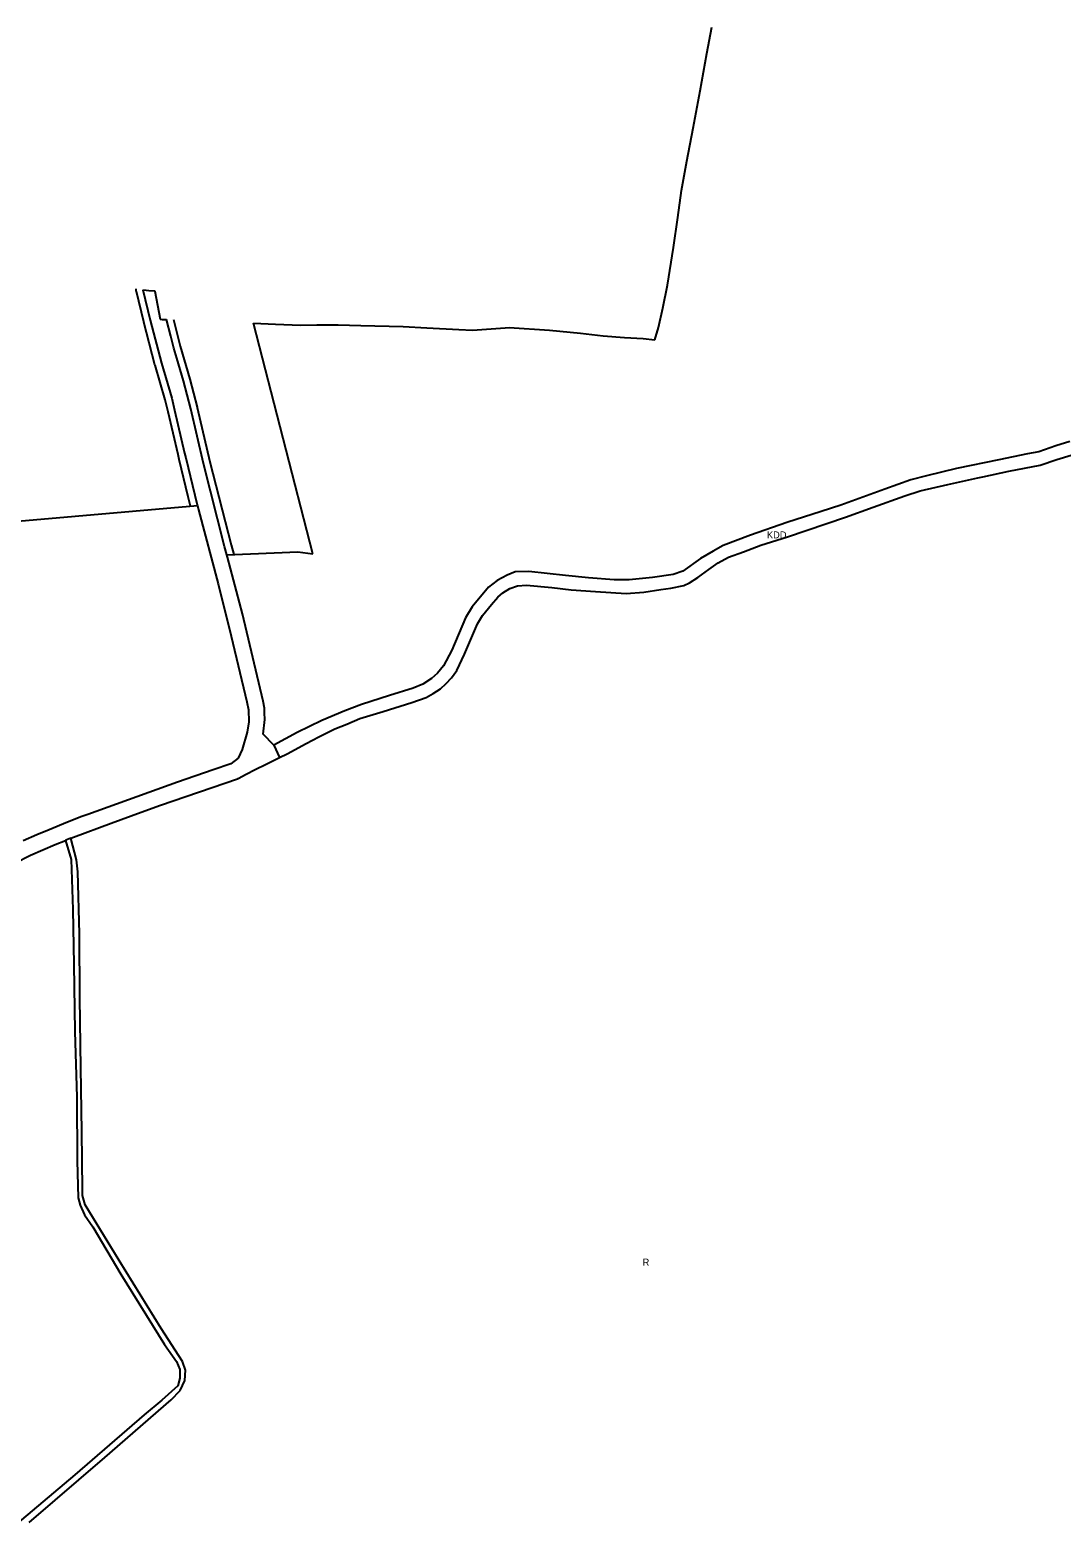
# Model space of a CAD drawing. Extents: x 7435758 to 7439981, y 5550649 to 5554049.
# Drawn here: x 7438238 to 7439010, y 5551717 to 5552845 of the extents above; entities that cross this region are included whole.
import ezdxf

# ---------------------------------------------------------------- set-up
doc = ezdxf.new("R2010")
doc.units = 0
for name, color, linetype in [('linie_rozgraniczające', 7, 'Continuous'), ('linie_zabudowy_nieprzekraczalne', 7, 'Continuous'), ('oznaczenia_przeznaczen', 7, 'Continuous')]:
    doc.layers.add(name, color=color, linetype=linetype)

msp = doc.modelspace()

# ---------------------------------------------------------------- linework, layer by layer
at = {"layer": 'linie_rozgraniczające'}
for p, q in [((7438744.68, 5552827.83), (7438748.26, 5552847.53)), ((7438739.56, 5552800.01), (7438744.68, 5552827.83)), ((7438734.37, 5552772.19), (7438739.56, 5552800.01)), ((7438729.69, 5552747.32), (7438734.37, 5552772.19)), ((7438725.79, 5552725.47), (7438729.69, 5552747.32)), ((7438722.9, 5552705.16), (7438725.79, 5552725.47)), ((7438719.67, 5552682.88), (7438722.9, 5552705.16)), ((7438715.25, 5552654.67), (7438719.67, 5552682.88)), ((7438711.74, 5552637.38), (7438715.25, 5552654.67)), ((7438322.72, 5552651.12), (7438328.21, 5552628.27)), ((7438322.72, 5552651.12), (7438325.27, 5552650.78)), ((7438325.27, 5552650.78), (7438327.16, 5552650.65)), ((7438327.16, 5552650.65), (7438331.61, 5552650.33)), ((7438331.61, 5552650.33), (7438331.68, 5552649.99)), ((7438331.68, 5552649.99), (7438335.75, 5552629.06)), ((7438708.52, 5552622.89), (7438711.74, 5552637.38)), ((7438328.21, 5552628.27), (7438336.63, 5552596.18)), ((7438335.75, 5552629.06), (7438337.23, 5552629)), ((7438337.23, 5552629), (7438340.17, 5552628.88)), ((7438340.17, 5552628.88), (7438340.45, 5552628.87)), ((7438343.56, 5552616.42), (7438340.45, 5552628.87)), ((7438449.92, 5552453.64), (7438405.44, 5552626.22)), ((7438405.44, 5552626.22), (7438421.86, 5552625.49)), ((7438421.86, 5552625.49), (7438440.58, 5552624.67)), ((7438440.58, 5552624.67), (7438452.74, 5552624.8)), ((7438452.74, 5552624.8), (7438468.8, 5552624.98)), ((7438468.8, 5552624.98), (7438485.76, 5552624.5)), ((7438485.76, 5552624.5), (7438517.51, 5552623.61)), ((7438517.51, 5552623.61), (7438535.23, 5552622.71)), ((7438535.23, 5552622.71), (7438559.17, 5552621.48)), ((7438559.17, 5552621.48), (7438569.23, 5552620.97)), ((7438569.23, 5552620.97), (7438593.66, 5552622.75)), ((7438593.66, 5552622.75), (7438596.63, 5552622.97)), ((7438596.63, 5552622.97), (7438626.87, 5552620.99)), ((7438626.87, 5552620.99), (7438650.03, 5552618.68)), ((7438705.83, 5552613.59), (7438708.52, 5552622.89)), ((7438345.77, 5552607.54), (7438343.56, 5552616.42)), ((7438650.03, 5552618.68), (7438667.19, 5552616.72)), ((7438667.19, 5552616.72), (7438683.12, 5552615.39)), ((7438683.12, 5552615.39), (7438697.04, 5552614.6)), ((7438697.04, 5552614.6), (7438705.83, 5552613.59)), ((7438348.01, 5552600.01), (7438345.77, 5552607.54)), ((7438353.1, 5552582.88), (7438348.01, 5552600.01)), ((7438348.01, 5552600.01), (7438348.01, 5552600.01)), ((7438336.63, 5552596.18), (7438344.29, 5552569.96)), ((7438358.55, 5552561.94), (7438353.1, 5552582.88)), ((7438344.29, 5552569.96), (7438346.43, 5552561.05)), ((7438346.43, 5552561.05), (7438353.93, 5552528.9)), ((7438367.99, 5552521.18), (7438358.55, 5552561.94)), ((7438992.94, 5552529.86), (7438984.57, 5552528.4)), ((7439005.75, 5552534.23), (7438992.94, 5552529.86)), ((7439016.18, 5552537.5), (7439005.75, 5552534.23)), ((7438353.93, 5552528.9), (7438354.75, 5552525.29)), ((7438354.75, 5552525.29), (7438361.51, 5552497.38)), ((7438383.86, 5552459.09), (7438367.99, 5552521.18)), ((7438963.04, 5552523.87), (7438931.43, 5552517.31)), ((7438984.57, 5552528.4), (7438963.04, 5552523.87)), ((7438970.59, 5552515.35), (7438994.06, 5552519.85)), ((7438994.06, 5552519.85), (7439006.47, 5552524.22)), ((7439006.47, 5552524.22), (7439017.3, 5552527.29)), ((7438897.36, 5552508.93), (7438877.74, 5552502.04)), ((7438909.02, 5552511.84), (7438897.36, 5552508.93)), ((7438931.43, 5552517.31), (7438909.02, 5552511.84)), ((7438924.91, 5552505.38), (7438947.45, 5552510.35)), ((7438947.45, 5552510.35), (7438951.13, 5552511.15)), ((7438951.13, 5552511.15), (7438970.59, 5552515.35)), ((7438361.51, 5552497.38), (7438363.37, 5552490.22)), ((7438877.74, 5552502.04), (7438844.94, 5552489.95)), ((7438869.06, 5552488.39), (7438892.66, 5552497.06)), ((7438892.66, 5552497.06), (7438904.29, 5552500.78)), ((7438904.29, 5552500.78), (7438924.91, 5552505.38)), ((7438223.43, 5552477.5), (7438363.49, 5552489.76)), ((7438363.37, 5552490.22), (7438363.49, 5552489.76)), ((7438363.49, 5552489.76), (7438364.33, 5552486.5)), ((7438364.33, 5552486.5), (7438378.95, 5552431.14)), ((7438830.21, 5552485.19), (7438804.56, 5552477.05)), ((7438844.94, 5552489.95), (7438830.21, 5552485.19)), ((7438848.25, 5552480.85), (7438869.06, 5552488.39)), ((7438804.56, 5552477.05), (7438777.33, 5552467.62)), ((7438804.9, 5552466.2), (7438848.25, 5552480.85)), ((7438777.33, 5552467.62), (7438756.74, 5552459.68)), ((7438785.05, 5552459.91), (7438804.9, 5552466.2)), ((7438385.56, 5552452.77), (7438383.86, 5552459.09)), ((7438385.56, 5552452.77), (7438438.57, 5552454.92)), ((7438386.03, 5552450.99), (7438385.56, 5552452.77)), ((7438397.17, 5552408.54), (7438386.03, 5552450.99)), ((7438438.57, 5552454.92), (7438449.92, 5552453.64)), ((7438749.3, 5552455.62), (7438739.98, 5552449.96)), ((7438756.74, 5552459.68), (7438749.3, 5552455.62)), ((7438753.21, 5552446.74), (7438760.96, 5552450.92)), ((7438760.96, 5552450.92), (7438772.06, 5552454.92)), ((7438772.06, 5552454.92), (7438785.05, 5552459.91)), ((7438601.22, 5552440.17), (7438595.23, 5552437.69)), ((7438611.56, 5552440.39), (7438601.22, 5552440.17)), ((7438638.89, 5552437.23), (7438611.56, 5552440.39)), ((7438726.77, 5552440.49), (7438719.55, 5552438.17)), ((7438739.98, 5552449.96), (7438726.77, 5552440.49)), ((7438737.82, 5552435.77), (7438746.1, 5552441.79)), ((7438746.1, 5552441.79), (7438753.21, 5552446.74)), ((7438378.95, 5552431.14), (7438388.86, 5552391.88)), ((7438581.18, 5552428.6), (7438569.1, 5552413.8)), ((7438587.88, 5552433.54), (7438581.18, 5552428.6)), ((7438595.23, 5552437.69), (7438587.88, 5552433.54)), ((7438597.26, 5552427.63), (7438602.86, 5552429.68)), ((7438602.86, 5552429.68), (7438609.74, 5552430.16)), ((7438609.74, 5552430.16), (7438628.59, 5552428.39)), ((7438628.59, 5552428.39), (7438643.08, 5552426.54)), ((7438656.02, 5552435.49), (7438638.89, 5552437.23)), ((7438675.36, 5552434.04), (7438656.02, 5552435.49)), ((7438686.63, 5552433.99), (7438675.36, 5552434.04)), ((7438704.01, 5552435.92), (7438686.63, 5552433.99)), ((7438719.55, 5552438.17), (7438704.01, 5552435.92)), ((7438717.64, 5552427.84), (7438727.5, 5552429.87)), ((7438727.5, 5552429.87), (7438731.68, 5552431.86)), ((7438731.68, 5552431.86), (7438737.82, 5552435.77)), ((7438583.53, 5552415.7), (7438588.18, 5552421.17)), ((7438588.18, 5552421.17), (7438592.11, 5552424.37)), ((7438592.11, 5552424.37), (7438597.26, 5552427.63)), ((7438643.08, 5552426.54), (7438661.41, 5552425.26)), ((7438661.41, 5552425.26), (7438684.2, 5552423.74)), ((7438684.2, 5552423.74), (7438697.56, 5552424.9)), ((7438697.56, 5552424.9), (7438710.17, 5552426.73)), ((7438710.17, 5552426.73), (7438717.64, 5552427.84)), ((7438412.69, 5552343.18), (7438397.17, 5552408.54)), ((7438564.15, 5552405.68), (7438553.96, 5552381.51)), ((7438569.1, 5552413.8), (7438564.15, 5552405.68)), ((7438573.16, 5552401.07), (7438576.76, 5552407.51)), ((7438576.76, 5552407.51), (7438583.53, 5552415.7)), ((7438563.32, 5552378.54), (7438573.16, 5552401.07)), ((7438388.86, 5552391.88), (7438400.52, 5552342.83)), ((7438553.96, 5552381.51), (7438547.54, 5552369.68)), ((7438557.52, 5552366.33), (7438563.32, 5552378.54)), ((7438543.19, 5552364.33), (7438538.68, 5552360.29)), ((7438547.54, 5552369.68), (7438543.19, 5552364.33)), ((7438549.7, 5552356.57), (7438553.49, 5552360.68)), ((7438553.49, 5552360.68), (7438557.52, 5552366.33)), ((7438524.97, 5552353.03), (7438507.13, 5552347.43)), ((7438532.16, 5552355.96), (7438524.97, 5552353.03)), ((7438538.68, 5552360.29), (7438532.16, 5552355.96)), ((7438534.69, 5552346.02), (7438539.85, 5552349.07)), ((7438539.85, 5552349.07), (7438545.39, 5552352.54)), ((7438545.39, 5552352.54), (7438549.7, 5552356.57)), ((7438400.52, 5552342.83), (7438401.75, 5552336.76)), ((7438413.7, 5552338.09), (7438412.69, 5552343.18)), ((7438413.82, 5552334.54), (7438413.7, 5552338.09)), ((7438486.29, 5552340.7), (7438473.69, 5552336.13)), ((7438507.13, 5552347.43), (7438486.29, 5552340.7)), ((7438502.43, 5552335.57), (7438523.88, 5552342.33)), ((7438523.88, 5552342.33), (7438534.69, 5552346.02)), ((7438402.02, 5552327.94), (7438400.8, 5552320.12)), ((7438401.75, 5552336.76), (7438402.02, 5552327.94)), ((7438412.72, 5552318.69), (7438413.98, 5552329.47)), ((7438413.98, 5552329.47), (7438413.82, 5552334.54)), ((7438456.62, 5552328.84), (7438438.11, 5552319.77)), ((7438473.69, 5552336.13), (7438456.62, 5552328.84)), ((7438475.41, 5552326.15), (7438484.99, 5552330.19)), ((7438484.99, 5552330.19), (7438502.43, 5552335.57)), ((7438400.8, 5552320.12), (7438397.03, 5552307.09)), ((7438420.65, 5552310.35), (7438412.72, 5552318.69)), ((7438438.11, 5552319.77), (7438420.65, 5552310.35)), ((7438445, 5552311.58), (7438454.38, 5552316.67)), ((7438454.38, 5552316.67), (7438466.32, 5552322.64)), ((7438466.32, 5552322.64), (7438475.41, 5552326.15)), ((7438397.03, 5552307.09), (7438393.96, 5552300.74)), ((7438420.65, 5552310.35), (7438424.93, 5552301.01)), ((7438430.74, 5552303.92), (7438445, 5552311.58)), ((7438388.52, 5552296.28), (7438375.38, 5552291.85)), ((7438393.96, 5552300.74), (7438388.52, 5552296.28)), ((7438406.66, 5552292.22), (7438415.03, 5552296.03)), ((7438415.03, 5552296.03), (7438424.93, 5552301.01)), ((7438424.93, 5552301.01), (7438430.74, 5552303.92)), ((7438348.58, 5552282.69), (7438281.6, 5552258.57)), ((7438335.94, 5552265.42), (7438393.4, 5552285.26)), ((7438375.38, 5552291.85), (7438348.58, 5552282.69)), ((7438393.4, 5552285.26), (7438393.55, 5552285.35)), ((7438393.55, 5552285.35), (7438394, 5552285.5)), ((7438394, 5552285.5), (7438399.99, 5552288.78)), ((7438399.99, 5552288.78), (7438406.66, 5552292.22)), ((7438298.99, 5552252.1), (7438321.51, 5552260.24)), ((7438321.51, 5552260.24), (7438335.94, 5552265.42)), ((7438266.33, 5552252.72), (7438252.54, 5552247.07)), ((7438277.12, 5552256.96), (7438266.33, 5552252.72)), ((7438270.73, 5552241.55), (7438298.99, 5552252.1)), ((7438277.13, 5552256.96), (7438277.12, 5552256.96)), ((7438281.6, 5552258.57), (7438277.13, 5552256.96)), ((7438243.46, 5552243.15), (7438233.29, 5552238.74)), ((7438252.54, 5552247.07), (7438243.46, 5552243.15)), ((7438257.14, 5552235.99), (7438264.74, 5552239.1)), ((7438265.08, 5552239.24), (7438264.74, 5552239.1)), ((7438264.74, 5552239.1), (7438269, 5552224.86)), ((7438268.72, 5552240.73), (7438265.08, 5552239.24)), ((7438268.72, 5552240.73), (7438270.73, 5552241.55)), ((7438272.96, 5552224.48), (7438268.72, 5552240.73)), ((7438226.89, 5552222), (7438238.58, 5552227.97)), ((7438238.58, 5552227.97), (7438257.14, 5552235.99)), ((7438269, 5552224.86), (7438270.34, 5552187.4)), ((7438273.96, 5552215.46), (7438272.96, 5552224.48)), ((7438275.21, 5552169.11), (7438273.96, 5552215.46)), ((7438270.34, 5552187.4), (7438271.11, 5552146.33)), ((7438275.64, 5552120.93), (7438275.21, 5552169.11)), ((7438271.11, 5552146.33), (7438271.8, 5552096.19)), ((7438276.4, 5552069.01), (7438275.64, 5552120.93)), ((7438271.8, 5552096.19), (7438273.35, 5552046.98)), ((7438276.99, 5552021.2), (7438276.4, 5552069.01)), ((7438273.35, 5552046.98), (7438273.57, 5551999.34)), ((7438277.58, 5551977.87), (7438276.99, 5552021.2)), ((7438273.57, 5551999.34), (7438274.25, 5551971.64)), ((7438277.59, 5551973.39), (7438277.58, 5551977.87)), ((7438274.25, 5551971.64), (7438275.73, 5551966.13)), ((7438275.73, 5551966.13), (7438279.07, 5551958.91)), ((7438279.66, 5551966.47), (7438277.59, 5551973.39)), ((7438304.96, 5551924.69), (7438279.66, 5551966.47)), ((7438279.07, 5551958.91), (7438285.18, 5551949.83)), ((7438285.18, 5551949.83), (7438306.27, 5551914.51)), ((7438336.37, 5551873.83), (7438304.96, 5551924.69)), ((7438306.27, 5551914.51), (7438339.01, 5551861.91)), ((7438352.27, 5551849.16), (7438336.37, 5551873.83)), ((7438339.01, 5551861.91), (7438347.87, 5551849.07)), ((7438347.87, 5551849.07), (7438350.26, 5551843.25)), ((7438350.26, 5551843.25), (7438350.35, 5551836.79)), ((7438354.69, 5551842.62), (7438352.27, 5551849.16)), ((7438354.1, 5551834.88), (7438354.69, 5551842.62)), ((7438348.79, 5551830.98), (7438337.02, 5551820.28)), ((7438350.35, 5551836.79), (7438348.79, 5551830.98)), ((7438350.63, 5551827.56), (7438354.1, 5551834.88)), ((7438294.16, 5551777.35), (7438344.01, 5551820.38)), ((7438337.02, 5551820.28), (7438323.65, 5551809.14)), ((7438344.01, 5551820.38), (7438350.63, 5551827.56)), ((7438323.65, 5551809.14), (7438271.71, 5551764.41)), ((7438237.71, 5551728.66), (7438294.16, 5551777.35)), ((7438271.71, 5551764.41), (7438215.92, 5551717.18))]:
    msp.add_line(p, q, dxfattribs=at)
at = {"layer": 'linie_zabudowy_nieprzekraczalne'}
for points in [[(7438358.45, 5552489.25), (7438356.67, 5552496.13), (7438356.65, 5552496.21), (7438349.89, 5552524.11), (7438349.89, 5552524.12), (7438349.87, 5552524.18), (7438349.05, 5552527.77), (7438341.56, 5552559.9), (7438339.46, 5552568.68), (7438331.83, 5552594.78), (7438331.79, 5552594.92), (7438323.38, 5552627), (7438323.35, 5552627.09), (7438323.35, 5552627.1), (7438317.86, 5552649.95), (7438317.86, 5552649.95), (7438317.8, 5552650.27), (7438317.75, 5552650.59), (7438317.73, 5552650.92), (7438317.73, 5552651.25), (7438317.74, 5552651.57), (7438317.77, 5552651.77)], [(7438345.6, 5552628.86), (7438350.59, 5552608.86), (7438357.89, 5552584.3), (7438357.94, 5552584.14), (7438363.39, 5552563.2), (7438363.41, 5552563.12), (7438363.42, 5552563.07), (7438372.85, 5552522.37), (7438388.69, 5552460.35), (7438390.69, 5552452.93)]]:
    msp.add_lwpolyline(points, dxfattribs=at)

# ---------------------------------------------------------------- texts
at = {"layer": 'oznaczenia_przeznaczen'}
for s, p in [('KDD', (7438789.55, 5552465.12)), ('R', (7438696.58, 5551920.87))]:
    msp.add_text(s, height=5.2, dxfattribs=at).set_placement(p)

doc.saveas('drawing.dxf')
